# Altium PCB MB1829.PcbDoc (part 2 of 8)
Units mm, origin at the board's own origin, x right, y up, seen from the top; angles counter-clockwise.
Board outline 90 x 110 mm, 6 copper layers (Top Layer, Signal Layer 1, Signal Layer 2, Signal Layer 3, Signal Layer 4, Bottom Layer), stack 1.578 mm thick; 466 components, 354 nets, 2058 pads, 1522 vias.
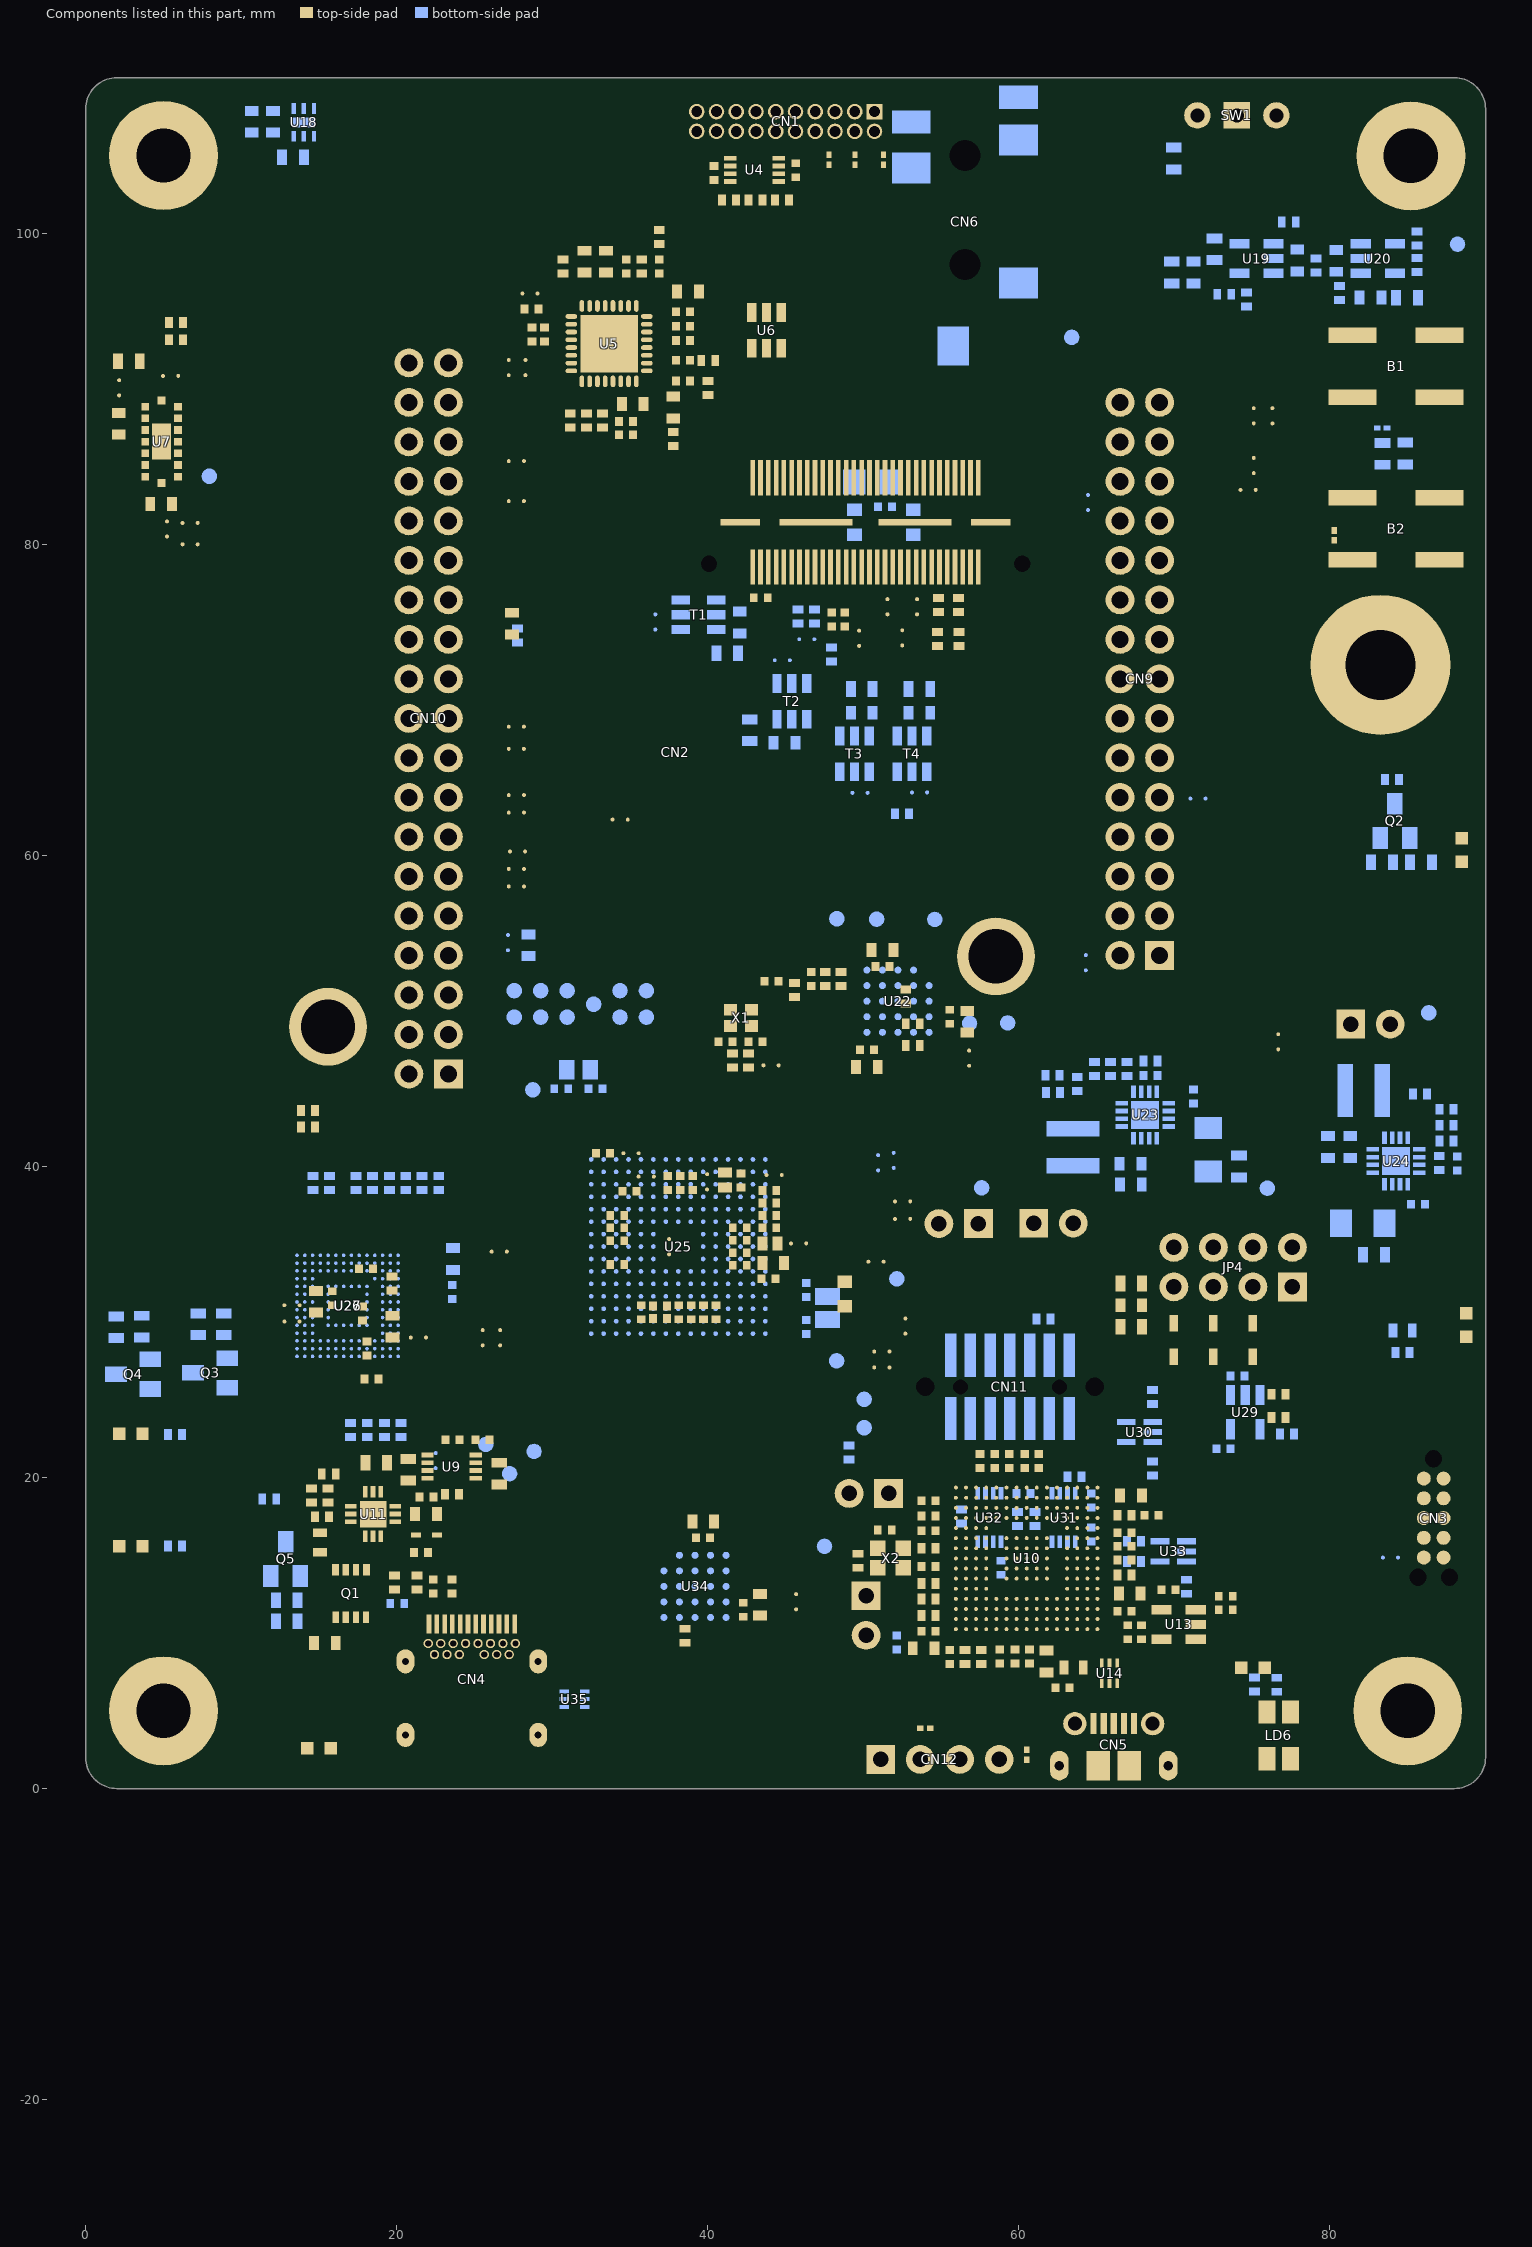
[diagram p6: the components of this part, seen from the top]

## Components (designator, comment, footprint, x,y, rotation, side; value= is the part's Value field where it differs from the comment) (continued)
LD3 "LED_green" LED_0603_OSRAM_LG-Q396-PS-35_GREEN_1A2K_H0P4 2.9,22.8 r180 top locked value=GREEN
LD4 "LED_red" LED_0603_OSRAM_LS-Q976-NR-1_RED_1A2K_H0P8 2.9,15.575 r180 top locked value=RED
LD5 "LED_red" LED_0603_OSRAM_LS-Q976-NR-1_RED_1A2K_H0P8 75.05,7.775 r0 top locked value=RED
LD6 "LED_BICOLOR" LED_BI-GR_WE-150141SV73110 76.7,3.425 r0 top locked value="Green / Red"
LD7 "LED_green" LED_0603_OSRAM_LG-Q396-PS-35_GREEN_1A2K_H0P4 15,2.6 r0 top locked value=GREEN
Q1 "STL11N3LLH6" MOS_POWERFLAT_3P3X3P3_P065 17.05,12.55 r0 top
Q2 "9013-SOT23" NPN_SOT23 84.175,62.225 r180 bottom value="NPN SOT23"
Q3 "9013-SOT23" NPN_SOT23 8,26.725 r270 bottom value="NPN SOT23"
Q4 "9013-SOT23" NPN_SOT23 3.047,26.641 r270 bottom value="NPN SOT23"
Q5 "9013-SOT23" NPN_SOT23 12.85,14.775 r180 bottom value="NPN SOT23"
R1 "Resistor" R0402 41.35,102.125 r0 top value=10K
R2 "Resistor" R0402 43.05,102.125 r0 top value=0R
R3 "Resistor" R0402 44.775,102.125 r180 top value=10K
R4 "Resistor" R0402 36.875,99.75 r270 top value=10K
R5 "Resistor" R0402 30.675,97.85 r270 top value=10K
R6 "Resistor" R0402 35.75,97.85 r270 top value=2K2
R7 "Resistor" R0402 5.8,94.25 r180 top value=1K8
R8 "Resistor" R0402 5.8,93.15 r180 top value=1K8
R9 "Resistor" R0603 2.775,91.775 r0 top value=10K
R10 "Resistor" R0402 40.025,91.825 r180 top value=51R
R11 "Resistor" R0402 40,90.05 r90 top value=51R
R12 "Resistor" R0402 33.225,87.95 r270 top value=10K
R13 "Resistor" R0402 31.15,87.95 r270 top value=1K8
R14 "Resistor" R0402 32.207,87.95 r270 top value=1K8
R15 "Resistor" R0402 37.775,86.775 r270 top value=0R
R16 "Resistor" R0402 54.825,76.1 r270 top value=0R
R17 "Resistor" R0402 56.125,76.1 r270 top value=0R
R18 "Resistor" R0402 56.15,73.925 r270 top value=0R
R19 "Resistor" R0402 54.775,73.9 r270 top value=0R
R20 "Resistor" R0402 47.55,52.05 r270 top value=10K
R21 "Resistor" R0402 48.55,52.05 r270 top value=10K
R22 "Resistor" R0402 45.567,51.355 r90 top value=0R
R23 "Resistor" R0402 52.725,50.925 r270 top value=0R
R24 "Resistor" R0402 53.175,49.175 r0 top value=0R
R25 "Resistor" R0402 53.175,47.775 r0 top value=10K
R26 "Resistor" R0402 42.625,46.8 r90 top value=0R
R27 "Resistor" R0402 41.575,46.8 r90 top value=0R
R28 "Resistor" R0402 14.3,43.6 r0 top value=1K8
R29 "Resistor" R0402 14.3,42.525 r0 top value=1K8
R30 "Resistor" R0402 19.7,32.475 r270 top value=47K
R31 "Resistor" R0603 67.225,32.475 r0 top value=330K
R32 "Resistor" R0603 67.225,29.7 r180 top value=27K
R33 "Resistor" R0402 76.7,25.35 r180 top value=100K
R34 "Resistor" R0402 76.7,23.85 r180 top value=1K
R35 "Resistor" R0603 20.725,20.5 r90 top value=47K
R36 "Resistor" R0603 18.675,20.95 r0 top value=10K
R37 "Resistor" R0603 26.6,20.25 r270 top value=47K
R38 "Resistor" R0402 15.625,20.225 r0 top value=3K9
R39 "Resistor" R0402 14.525,18.85 r270 top value=3K9
R40 "Resistor" R0402 15.575,18.85 r270 top value=1K2
R41 "Resistor" R0402 23.55,18.925 r180 top value=0R
R42 "Resistor" R0402 66.8,17.575 r0 top value=100R
R43 "Resistor" R0402 15.2,17.475 r0 top value=1K2
R44 "Resistor" R0402 54.2,15.45 r0 top value=100R
R45 "Resistor" R0402 49.65,14.65 r270 top value=10K
R46 "Resistor" R0402 66.8,13.725 r180 top value=3K
R47 "Resistor" R0402 19.85,13.25 r270 top value=2K4
R48 "Resistor" R0402 21.3,13.25 r270 top value=10K
R49 "Resistor" R0402 54.2,13.175 r0 top value=10K
R50 "Resistor" R0402 54.2,12.2 r180 top value=4K7
R51 "Resistor" R0402 54.2,11.125 r180 top value=4K7
R52 "Resistor" R0402 38.525,9.825 r270 top value=10K
R53 "Resistor" R0402 56.525,8.45 r90 top value=4K7
R54 "Resistor" R0402 57.575,8.45 r90 top value=2K7
R55 "Resistor" R0603 69.95,104.8 r90 bottom value=10K
R56 "Resistor" R0603 13.326,104.875 r180 bottom value=10K
R57 "Resistor" R0402 77.35,100.725 r180 bottom value=0R
R58 "Resistor" R0402 85.6,99.675 r270 bottom value=160K
R59 "Resistor" R0603 72.575,98.975 r270 bottom value=0R
R60 "Resistor" R0402 85.591,97.95 r270 bottom value=220K
R61 "Resistor" R0402 79.1,97.923 r90 bottom value=0R
R62 "Resistor" R0603 69.825,97.475 r90 bottom value=0R
R63 "Resistor" R0402 80.6,96.15 r90 bottom value=0R
R64 "Resistor" R0402 74.625,95.75 r90 bottom value=160K
R65 "Resistor" R0402 73.2,96.075 r180 bottom value=82K
R66 "Resistor" R0603 84.95,95.85 r180 bottom value=0R
R67 "Resistor" R0603 84.85,85.84 r90 bottom value=20K
R68 "Resistor" R0603 83.375,85.815 r90 bottom value=200R
R69 "Resistor" R0402 46.85,75.346 r90 bottom value=3K3
R70 "Resistor" R0402 45.8,75.346 r90 bottom value=3K3
R71 "Resistor" R0402 27.75,74.15 r270 bottom value=10K
R72 "Resistor" R0402 47.95,72.921 r90 bottom value=10K
R73 "Resistor" R0603 41.25,72.996 r180 bottom value=0R
R74 "Resistor" R0603 53.6,70.696 r0 bottom value=0R
R75 "Resistor" R0603 49.9,70.696 r0 bottom value=0R
R76 "Resistor" R0603 42.7,68.046 r90 bottom value=0R
R77 "Resistor" R0402 83.996,64.879 r180 bottom value=270R
R78 "Resistor" R0402 52.475,62.675 r0 bottom value=100K
R79 "Resistor" R0603 85.85,59.55 r180 bottom value=47K
R80 "Resistor" R0603 83.35,59.55 r0 bottom value=100K
R81 "Resistor" R0402 68.472,46.791 r0 bottom value=0R
R82 "Resistor" R0402 66.947,46.266 r270 bottom value=15K
R83 "Resistor" R0402 65.897,46.266 r90 bottom value=6K8
R84 "Resistor" R0402 64.847,46.266 r90 bottom value=12K
R85 "Resistor" R0402 62.172,45.866 r0 bottom value=0R
R86 "Resistor" R0402 63.747,45.291 r90 bottom value=100K
R87 "Resistor" R0402 62.197,44.766 r0 bottom value=1K
R88 "Resistor" R0402 85.8,44.65 r0 bottom value=100K
R89 "Resistor" R0402 87.5,43.675 r180 bottom value=0R
R90 "Resistor" R0402 87.5,42.65 r0 bottom value=47K
R91 "Resistor" R0402 87.5,41.625 r180 bottom value=15K
R92 "Resistor" R0603 74.15,40 r90 bottom value=0R
R93 "Resistor" R0402 87.025,40.225 r270 bottom value=0R
R95 "Resistor" R0402 22.7,38.925 r90 bottom value=47K
R96 "Resistor" R0402 21.625,38.925 r90 bottom value=47K
R97 "Resistor" R0402 20.575,38.925 r90 bottom value=47K
R98 "Resistor" R0402 19.525,38.925 r90 bottom value=47K
R99 "Resistor" R0402 18.45,38.925 r90 bottom value=47K
R100 "Resistor" R0402 17.375,38.925 r90 bottom value=47K
R101 "Resistor" R0402 15.675,38.925 r90 bottom value=47K
R102 "Resistor" R0402 14.625,38.925 r90 bottom value=47K
R103 "Resistor" R0603 82.825,34.325 r0 bottom value=0R
R104 "Resistor" R0603 8.875,29.85 r270 bottom value=100K
R105 "Resistor" R0603 7.225,29.85 r270 bottom value=47K
R106 "Resistor" R0603 3.6,29.7 r270 bottom value=100K
R107 "Resistor" R0603 1.972,29.666 r270 bottom value=47K
R108 "Resistor" R0402 61.575,30.2 r0 bottom value=100R
R109 "Resistor" R0402 84.65,28.05 r180 bottom value=620R
R110 "Resistor" R0402 68.6,25.175 r270 bottom value=47R
R111 "Resistor" R0402 20.275,23.05 r90 bottom value=0R
R112 "Resistor" R0402 19.2,23.05 r270 bottom value=10K
R113 "Resistor" R0402 18.1,23.05 r270 bottom value=10K
R114 "Resistor" R0402 17.025,23.05 r270 bottom value=10K
R115 "Resistor" R0402 77.25,22.8 r180 bottom value=10K
R116 "Resistor" R0402 5.75,22.775 r0 bottom value=270R
R117 "Resistor" R0402 49.075,21.6 r270 bottom value=47R
R118 "Resistor" R0402 68.6,20.575 r270 bottom value=47R
R119 "Resistor" R0402 63.575,20.05 r180 bottom value=100K
R120 "Resistor" R0402 11.8,18.625 r0 bottom value=270R
R121 "Resistor" R0402 56.3,17.5 r270 bottom value=0R
R122 "Resistor" R0402 61.025,17.325 r270 bottom value=0R
R123 "Resistor" R0402 59.9,17.325 r270 bottom value=100R
R124 "Resistor" R0402 67.4,15.9 r180 bottom value=47R
R125 "Resistor" R0402 5.75,15.6 r0 bottom value=270R
R126 "Resistor" R0402 67.4,14.6 r180 bottom value=47R
R127 "Resistor" R0402 70.775,12.975 r270 bottom value=47R
R128 "Resistor" R0603 12.925,12.1 r0 bottom value=22K
R129 "Resistor" R0603 12.925,10.75 r0 bottom value=47K
R130 "Resistor" R0402 75.15,6.7 r90 bottom value=1K
R131 "Resistor" R0402 76.575,6.675 r90 bottom value=330R
SB1 "SB_OFF" SOLDER-BRIDGE_R0402-0R 28.525,96.125 r0 top
SB2 "SB_OFF" SOLDER-BRIDGE_R0402-0R 28.275,91.325 r90 top
SB3 "SB_OFF" SOLDER-BRIDGE_R0402-0R 27.2,91.325 r90 top
SB4 "SB_ON" SOLDER-BRIDGE_R0402-0R 5.5,90.825 r180 top
SB5 "SB_ON" SOLDER-BRIDGE_R0402-0R 2.15,90.1 r270 top
SB6 "SB_ON" SOLDER-BRIDGE_R0402-0R 76.3,88.3 r270 top
SB7 "SB_OFF" SOLDER-BRIDGE_R0402-0R 75.1,88.3 r270 top
SB8 "SB_OFF" SOLDER-BRIDGE_R0402-0R 75.1,85.1 r270 top
SB9 "SB_ON" SOLDER-BRIDGE_R0402-0R 74.7,83.5 r0 top
SB10 "SB_OFF" SOLDER-BRIDGE_R0402-0R 27.725,85.35 r180 top
SB11 "SB_OFF" SOLDER-BRIDGE_R0402-0R 27.725,82.775 r180 top
SB12 "SB_OFF" SOLDER-BRIDGE_R0402-0R 5.225,80.95 r90 top
SB13 "SB_OFF" SOLDER-BRIDGE_R0402-0R 6.75,81.375 r180 top
SB14 "SB_OFF" SOLDER-BRIDGE_R0402-0R 51.55,76.021 r270 top
SB15 "SB_OFF" SOLDER-BRIDGE_R0402-0R 53.45,76.021 r270 top
SB16 "SB_OFF" SOLDER-BRIDGE_R0402-0R 52.5,74.021 r270 top
SB17 "SB_OFF" SOLDER-BRIDGE_R0402-0R 34.4,62.3 r180 top
SB18 "SB_OFF" SOLDER-BRIDGE_R0402-0R 49.725,73.996 r270 top
SB19 "SB_OFF" SOLDER-BRIDGE_R0402-0R 27.725,60.25 r0 top
SB20 "SB_ON" SOLDER-BRIDGE_R0402-0R 27.725,68.275 r180 top
SB21 "SB_ON" SOLDER-BRIDGE_R0402-0R 27.725,66.85 r180 top
SB22 "SB_OFF" SOLDER-BRIDGE_R0402-0R 27.725,63.875 r180 top
SB23 "SB_ON" SOLDER-BRIDGE_R0402-0R 27.725,62.75 r180 top
SB24 "SB_ON" SOLDER-BRIDGE_R0402-0R 27.725,59.125 r180 top
SB25 "SB_OFF" SOLDER-BRIDGE_R0402-0R 27.725,58 r180 top
SB26 "SB_ON" SOLDER-BRIDGE_R0402-0R 76.675,47.975 r90 top
SB27 "SB_ON" SOLDER-BRIDGE_R0402-0R 56.8,46.925 r90 top
SB28 "SB_OFF" SOLDER-BRIDGE_R0402-0R 44.1,46.5 r180 top
SB29 "SB_ON" SOLDER-BRIDGE_R0402-0R 35.1,40.85 r180 top
SB30 "SB_ON" SOLDER-BRIDGE_R0402-0R 39.95,39.05 r270 top
SB31 "SB_ON" SOLDER-BRIDGE_R0402-0R 44.225,39.45 r0 top
SB32 "SB_ON" SOLDER-BRIDGE_R0402-0R 36,39.35 r0 top
SB33 "SB_ON" SOLDER-BRIDGE_R0402-0R 52.563,37.75 r180 top
SB34 "SB_OFF" SOLDER-BRIDGE_R0402-0R 52.563,36.625 r180 top
SB35 "SB_OFF" SOLDER-BRIDGE_R0402-0R 37.506,34.875 r270 top
SB36 "SB_ON" SOLDER-BRIDGE_R0402-0R 45.875,35.05 r180 top
SB37 "SB_ON" SOLDER-BRIDGE_R0402-0R 26.55,34.525 r0 top
SB38 "SB_OFF" SOLDER-BRIDGE_R0402-0R 50.772,33.875 r0 top
SB39 "SB_OFF" SOLDER-BRIDGE_R0402-0R 13.225,31.075 r0 top
SB40 "SB_OFF" SOLDER-BRIDGE_R0402-0R 52.7,29.775 r270 top
SB41 "SB_ON" SOLDER-BRIDGE_R0402-0R 13.225,30.025 r0 top
SB42 "SB_ON" SOLDER-BRIDGE_R0402-0R 25.525,28.95 r90 top
SB43 "SB_OFF" SOLDER-BRIDGE_R0402-0R 26.65,28.95 r90 top
SB44 "SB_ON" SOLDER-BRIDGE_R0402-0R 21.425,29 r180 top
SB45 "SB_ON" SOLDER-BRIDGE_R0402-0R 51.225,28.1 r180 top
SB46 "SB_OFF" SOLDER-BRIDGE_R0402-0R 51.225,27.075 r180 top
SB47 "SB_ON" SOLDER-BRIDGE_R0402-0R 45.675,11.975 r90 top
SB48 "SB_ON" SOLDER-BRIDGE_R0402-0R 64.45,82.725 r270 bottom
SB49 "SB_ON" SOLDER-BRIDGE_R0402-0R 36.625,74.971 r90 bottom
SB50 "SB_ON" SOLDER-BRIDGE_R0402-0R 46.325,73.896 r0 bottom
SB51 "SB_ON" SOLDER-BRIDGE_R0402-0R 44.75,72.546 r0 bottom
SB52 "SB_ON" SOLDER-BRIDGE_R0402-0R 53.65,64.046 r180 bottom
SB53 "SB_ON" SOLDER-BRIDGE_R0402-0R 49.825,64.021 r180 bottom
SB54 "SB_ON" SOLDER-BRIDGE_R0402-0R 71.55,63.65 r180 bottom
SB55 "SB_ON" SOLDER-BRIDGE_R0402-0R 27.15,54.35 r90 bottom
SB56 "SB_ON" SOLDER-BRIDGE_R0402-0R 64.3,53.063 r90 bottom
SB57 "SB_ON" SOLDER-BRIDGE_R0402-0R 51.95,40.427 r270 bottom
SB58 "SB_ON" SOLDER-BRIDGE_R0402-0R 50.95,40.2 r90 bottom
SB59 "SB_ON" SOLDER-BRIDGE_R0402-0R 22.5,21.05 r90 bottom
SB60 "SB_ON" SOLDER-BRIDGE_R0402-0R 6.75,80 r180 top
SB61 "SB_ON" SOLDER-BRIDGE_R0402-0R 83.85,14.85 r0 bottom
SW1 "SW_MECA_1K2" SWI_EAO_09-03290-01_EXTENDED_STRAIGHT_BLACK 74.015,107.575 r270 bottom value="Mechanical Slide Switch 1K2"
T1 "PMN30XP" MOS_SOT23-6L 39.4,75.471 r270 bottom
T2 "PMN30XP" MOS_SOT23-6L 45.4,69.896 r180 bottom
T3 "PMN30XP" MOS_SOT23-6L 49.425,66.521 r0 bottom
T4 "PMN30XP" MOS_SOT23-6L 53.125,66.521 r0 bottom
TP1 "Test Point" TP_SMD_1MM 88.2,99.3 r180 bottom
TP2 "Test Point" TP_SMD_1MM 63.394,93.3 r270 bottom
TP3 "Test Point" TP_SMD_1MM 7.95,84.375 r270 bottom
TP4 "Test Point" TP_SMD_1MM 48.3,55.925 r0 bottom
TP5 "Test Point" TP_SMD_1MM 50.85,55.9 r0 bottom
TP6 "Test Point" TP_SMD_1MM 54.592,55.879 r0 bottom
TP7 "Test Point" TP_SMD_1MM 36.053,51.304 r270 bottom
TP8 "Test Point" TP_SMD_1MM 34.353,51.304 r270 bottom
TP9 "Test Point" TP_SMD_1MM 30.953,51.304 r270 bottom
TP10 "Test Point" TP_SMD_1MM 29.253,51.304 r270 bottom
TP11 "Test Point" TP_SMD_1MM 27.553,51.304 r270 bottom
TP12 "Test Point" TP_SMD_1MM 32.653,50.429 r270 bottom
TP13 "Test Point" TP_SMD_1MM 86.35,49.875 r180 bottom
TP14 "Test Point" TP_SMD_1MM 36.053,49.604 r270 bottom
TP15 "Test Point" TP_SMD_1MM 34.353,49.604 r270 bottom
TP16 "Test Point" TP_SMD_1MM 30.953,49.604 r270 bottom
TP17 "Test Point" TP_SMD_1MM 29.253,49.604 r270 bottom
TP18 "Test Point" TP_SMD_1MM 27.553,49.604 r270 bottom
TP19 "Test Point" TP_SMD_1MM 59.275,49.225 r180 bottom
TP20 "Test Point" TP_SMD_1MM 56.825,49.2 r270 bottom
TP21 "Test Point" TP_SMD_1MM 28.75,44.925 r0 bottom
TP22 "Test Point" TP_SMD_1MM 57.6,38.625 r0 bottom
TP23 "Test Point" TP_SMD_1MM 75.975,38.6 r270 bottom
TP24 "Test Point" TP_SMD_1MM 52.152,32.774 r0 bottom
TP25 "Test Point" TP_SMD_1MM 48.275,27.5 r0 bottom
TP26 "Test Point" TP_SMD_1MM 50.05,25.025 r90 bottom
TP27 "Test Point" TP_SMD_1MM 50.05,23.2 r90 bottom
TP28 "Test Point" TP_SMD_1MM 25.728,22.125 r0 bottom
TP29 "Test Point" TP_SMD_1MM 28.825,21.675 r90 bottom
TP30 "Test Point" TP_SMD_1MM 27.25,20.25 r90 bottom
TP31 "Test Point" TP_SMD_1MM 47.5,15.575 r0 bottom
U1 "ESD-TRANSIL" ESD_ST0201 47.8,104.725 r270 top value=ESDALC6V1-1U2
U2 "ESD-TRANSIL" ESD_ST0201 49.45,104.725 r270 top value=ESDALC6V1-1U2
U3 "ESD-TRANSIL" ESD_ST0201 51.3,104.725 r270 top value=ESDALC6V1-1U2
U4 "SN74LVC2T45DCUT" ICC_VSSOP8_DCU_R-PDSO-G8_2X2P30_P050 43,104.075 r90 top
U5 "CS42L51-CNZ" ICC_QFN32-EPAD_5X5_P050 33.65,92.9 r0 top
U6 "ESDA6V1BC6" ESD_SOT23-6L 43.775,93.75 r180 top
U7 "VL53L5CXV0GC/1" ICC_LGA16_6P4X3_P075_H1P5 4.875,86.6 r270 top
U8 "ESD-TRANSIL" ESD_ST0201 80.275,80.575 r270 top value=ESDALC6V1-1U2
U9 "SN74LVC2T45DCUT" ICC_VSSOP8_DCU_R-PDSO-G8_2X2P30_P050 23.525,20.7 r270 top
U10 "ST-LINKV3E_SWD" ICC_UFBGA201_176+25_10X10_P065 60.5,14.8 r0 top
U11 "TCPP01-M12" ICC_QFN12L-EPAD_3X3_P050 18.475,17.65 r270 top
U12 "ESD-TRANSIL" ESD_QFN1610_2N_1K_2A 15.05,15.825 r90 top value=ESDA25P35-1U1M
U13 "LD3985M33R" REG_SOT23-5L 70.275,10.55 r90 top
U14 "ECMF02-2AMX6" ESD_QFN-6L_1P7X1P5_P050 65.825,7.425 r180 top
U15 "ESD-TRANSIL" ESD_QFN1610_2N_1K_2A 63.525,7.775 r180 top value=ESDA7P120-1U1M
U16 "ESD-TRANSIL" ESD_ST0201 53.975,3.875 r0 top value=ESDALC6V1-1U2
U17 "ESD-TRANSIL" ESD_ST0201 60.5,2.175 r90 top value=ESDALC6V1-1U2
U18 "STTS22H" ICC_UDFN6-EPAD_2X2_P065 14.025,107.125 r180 bottom
U19 "TPS76301" ICC_SOT23-5L_H1P45 75.275,98.375 r270 bottom
U20 "TPS76301" ICC_SOT23-5L_H1P45 83.075,98.375 r90 bottom
U21 "ESD-TRANSIL" ESD_ST0201 83.35,87.475 r180 bottom value=ESDALC6V1-1U2
U22 "MX25xx51245GXDx00" ICC_BGA24_5X5-BALL-ARRAY_6X8_P1 52.225,50.625 r180 bottom value=MX25UM51245GXDI00
U23 "TPS62140RGTR" ICC_VQFN16-EPAD_3X3_P050 68.122,43.314 r90 bottom value=TPS62140
U24 "TPS62140RGTR" ICC_VQFN16-EPAD_3X3_P050 84.25,40.35 r0 bottom value=TPS62140
U25 "STM32U599NJH6Q_BGA216_SMPS" ICC_TFBGA216_13X13_P080_H1P10_CODE-A0L2 38.1,34.85 r270 bottom locked value=STM32U599NJH6Q
U26 "MTFC4GACAJCN-1M WT" ICC_P-WFBGA153_13X11P5_P050 16.835,31.036 r270 bottom
U27 "eMMC_THGBMTG5D1LBAIL" ICC_P-WFBGA153_13X11P5_P050 16.835,31.036 r270 bottom value=THGBMTG5D1LBAIL
U28 "ESD-TRANSIL" ESD_QFN1610_2N_1K_2A 84.675,29.45 r0 bottom value=ESDA7P120-1U1M
U29 "STMPS2151STR" MOS_SOT23-5L 74.55,24.2 r0 bottom
U30 "ESDALC6V1W5" ESD_SOT323-5L 67.75,22.925 r270 bottom
U31 "SN74LVC2T45DCUT" ICC_VSSOP8_DCU_R-PDSO-G8_2X2P30_P050 62.875,17.425 r180 bottom
U32 "SN74LVC2T45DCUT" ICC_VSSOP8_DCU_R-PDSO-G8_2X2P30_P050 58.1,17.425 r180 bottom
U33 "ESDALC6V1W5" ESD_SOT323-5L 69.925,15.25 r270 bottom
U34 "APS256XXN-OBR-BG" ICC_BGA24_5X5-BALL-ARRAY_6X8_P1 39.175,13 r270 bottom value=APS512XXN-OBR-BG
U35 "ECMF02-2AMX6" ESD_QFN-6L_1P7X1P5_P050 31.425,5.75 r270 bottom
X1 "XTAL_4_PINS" CRY_NX2016SA_4P 42.125,49.55 r180 top value=16MHz
X2 "OSCILLATOR_4_PINS" OSC_NDK_NZ2520SB_4P 51.75,14.825 r0 top value=25MHz
X3 "XTAL_2_PINS" CRY_NX2012SA_2P 31.675,46.225 r180 bottom value=32.768KHz

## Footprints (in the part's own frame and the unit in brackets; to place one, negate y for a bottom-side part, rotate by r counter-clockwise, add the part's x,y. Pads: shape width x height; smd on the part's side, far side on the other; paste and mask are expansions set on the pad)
C0402 [mm]
  rect 0.51x0.56 smd mask+0.05: 1(-0.45,0) 2(0.45,0)
  body extent -0.5,-0.3 0.5,0.3, height 0.4
C0603 [mm]
  rect 0.64x0.89 smd mask+0.05: 1(-0.7,0) 2(0.7,0)
  silkscreen extent -0.9,-0.55 1.05,0.55, body extent -0.9,-0.5 0.9,0.5, height 1.4
C0603_H0P8 [mm] "MCD-01540"
  rect 0.64x0.89 smd mask+0.05: 1(-0.7,0) 2(0.7,0)
  silkscreen extent -0.9,-0.55 0.9,0.55, body extent -0.9,-0.5 0.9,0.5, height 1
C1206_H1P6 [mm]
  rect 1.4x1.78 smd mask+0.05: 1(-1.4,0) 2(1.4,0)
  silkscreen extent -2.12,-0.97 2.15,0.97, body extent -1.7,-0.9 1.7,0.9, height 1.8
CON_FCI_20021311-XXX20XXLF [mm]
  rect 1x1 / inner round 1 / far side rect 1x1 hole 0.7 mask+0.05: 1(5.715,0.635)
  round 1 hole 0.7 mask+0.05: 2(5.715,-0.635) 3(4.445,0.635) 4(4.445,-0.635) 5(3.175,0.635) 6(3.175,-0.635) 7(1.905,0.635) 8(1.905,-0.635) 9(0.635,0.635) 10(0.635,-0.635) 11(-0.635,0.635) 12(-0.635,-0.635) 13(-1.905,0.635) 14(-1.905,-0.635) 15(-3.175,0.635) 16(-3.175,-0.635) 17(-4.445,0.635) 18(-4.445,-0.635) 19(-5.715,0.635) 20(-5.715,-0.635)
  silkscreen extent -6.58,-1.5 6.58,1.5, body extent -6.58,-1.5 6.58,1.5, height 4.4
CON_PHONE-JACK-3P5_HY_PJ3028B [mm]
  rect 1.5x2.5 smd mask+0.05: 2(1.25,-3.45) 7(2.85,3.45)
  rect 2x2.5 smd mask+0.05: 3(4,-3.45) 4(5.8,3.45) 6(13.2,-3.45)
  rect 2.5x2 smd mask+0.05: 5(17.25,0.75)
  round 0.5 hole 2 unplated mask+0.1: MT1(5,0) MT2(12,0)
  Multi-Layer keep-out circle w0.01: c12,0 r1.25
  Multi-Layer keep-out circle w0.01: c5,0 r1.25
  silkscreen extent -0.9,-3.7 16,3, body extent -0.9,-3 16,3, height 5
CON_SAMTEC_QSH-030-01-F-D-A_NO-LCD-MB1835 [mm] "MCD-02128"
  round 5 hole 3.2: 1(3.5,3.5) PTH2(46.44,8.031)
  rect 0.3x2.27 smd mask+0.05: 1(45.31,38.801) 2(45.31,33.061) 3(44.81,38.801) 4(44.81,33.061) 5(44.31,38.801) 6(44.31,33.061) 7(43.81,38.801) 8(43.81,33.061) 9(43.31,38.801) 10(43.31,33.061) 11(42.81,38.801) 12(42.81,33.061) 13(42.31,38.801) 14(42.31,33.061) 15(41.81,38.801) 16(41.81,33.061) 17(41.31,38.801) 18(41.31,33.061) 19(40.81,38.801) 20(40.81,33.061) 21(40.31,38.801) 22(40.31,33.061) 23(39.81,38.801) 24(39.81,33.061) 25(39.31,38.801) 26(39.31,33.061) 27(38.81,38.801) 28(38.81,33.061) 29(38.31,38.801) 30(38.31,33.061) 31(37.81,38.801) 32(37.81,33.061) 33(37.31,38.801) 34(37.31,33.061) 35(36.81,38.801) 36(36.81,33.061) 37(36.31,38.801) 38(36.31,33.061) 39(35.81,38.801) 40(35.81,33.061) 41(35.31,38.801) 42(35.31,33.061) 43(34.81,38.801) 44(34.81,33.061) 45(34.31,38.801) 46(34.31,33.061) 47(33.81,38.801) 48(33.81,33.061) 49(33.31,38.801) 50(33.31,33.061) 51(32.81,38.801) 52(32.81,33.061) 53(32.31,38.801) 54(32.31,33.061) 55(31.81,38.801) 56(31.81,33.061) 57(31.31,38.801) 58(31.31,33.061) 59(30.81,38.801) 60(30.81,33.061)
  rect 2.54x0.43 smd mask+0.05: 61(46.122,35.931) 64(29.997,35.931)
  rect 4.7x0.43 smd mask+0.05: 62(41.235,35.931) 63(34.885,35.931)
  round 0.5 hole 1.05 unplated mask+0.1: 65(27.995,33.261) 66(48.125,33.261)
  Multi-Layer keep-out circle w0.01: c48.125,33.261 r0.801
  Multi-Layer keep-out circle w0.01: c27.995,33.261 r0.801
  silkscreen extent 27.26,32.23 48.86,39.63, body extent 27.4,32.18 48.72,39.68, height 4.97
CON_SAMTEC_SSW-115-21-F-D [mm] "MCD-02943"
  rect 1.85x1.85 / inner round 1.85 / far side rect 1.85x1.85 hole 1.1 mask+0.05: 1(17.78,-1.27)
  round 1.85 hole 1.1 mask+0.05: 2(17.78,1.27) 3(15.24,-1.27) 4(15.24,1.27) 5(12.7,-1.27) 6(12.7,1.27) 7(10.16,-1.27) 8(10.16,1.27) 9(7.62,-1.27) 10(7.62,1.27) 11(5.08,-1.27) 12(5.08,1.27) 13(2.54,-1.27) 14(2.54,1.27) 15(0,-1.27) 16(0,1.27) 17(-2.54,-1.27) 18(-2.54,1.27) 19(-5.08,-1.27) 20(-5.08,1.27) 21(-7.62,-1.27) 22(-7.62,1.27) 23(-10.16,-1.27) 24(-10.16,1.27) 25(-12.7,-1.27) 26(-12.7,1.27) 27(-15.24,-1.27) 28(-15.24,1.27) 29(-17.78,-1.27) 30(-17.78,1.27)
  silkscreen extent -19.31,-2.47 19.31,2.47, body extent -19.3,-2.48 19.3,2.48, height 8.51
CON_SAMTEC_SSW-119-21-F-D [mm] "MCD-02944"
  rect 1.85x1.85 / inner round 1.85 / far side rect 1.85x1.85 hole 1.1 mask+0.05: 1(22.86,-1.27)
  round 1.85 hole 1.1 mask+0.05: 2(22.86,1.27) 3(20.32,-1.27) 4(20.32,1.27) 5(17.78,-1.27) 6(17.78,1.27) 7(15.24,-1.27) 8(15.24,1.27) 9(12.7,-1.27) 10(12.7,1.27) 11(10.16,-1.27) 12(10.16,1.27) 13(7.62,-1.27) 14(7.62,1.27) 15(5.08,-1.27) 16(5.08,1.27) 17(2.54,-1.27) 18(2.54,1.27) 19(0,-1.27) 20(0,1.27) 21(-2.54,-1.27) 22(-2.54,1.27) 23(-5.08,-1.27) 24(-5.08,1.27) 25(-7.62,-1.27) 26(-7.62,1.27) 27(-10.16,-1.27) 28(-10.16,1.27) 29(-12.7,-1.27) 30(-12.7,1.27) 31(-15.24,-1.27) 32(-15.24,1.27) 33(-17.78,-1.27) 34(-17.78,1.27) 35(-20.32,-1.27) 36(-20.32,1.27) 37(-22.86,-1.27) 38(-22.86,1.27)
  silkscreen extent -24.39,-2.47 24.39,2.47, body extent -24.38,-2.48 24.38,2.48, height 8.51
CON_SAMTEC_TSW-102-07-G-S [mm]
  rect 1.85x1.85 / inner round 1.85 / far side rect 1.85x1.85 hole 1 mask+0.05: 1(-1.27,0)
  round 1.85 hole 1 mask+0.05: 2(1.27,0)
  silkscreen extent -2.58,-1.3 2.58,1.3, body extent -2.67,-1.3 2.58,1.3, height 8.38
CON_SAMTEC_TSW-104-07-G-S [mm]
  rect 1.85x1.85 / inner round 1.85 / far side rect 1.85x1.85 hole 1 mask+0.05: 1(-3.81,0)
  round 1.85 hole 1 mask+0.05: 2(-1.27,0) 3(1.27,0) 4(3.81,0)
  silkscreen extent -5.12,-1.3 5.12,1.3, body extent -5.21,-1.37 5.18,1.37, height 8.38
CON_SAMTEC_TSW-104-07-X-D [mm]
  rect 1.85x1.85 / inner round 1.85 / far side rect 1.85x1.85 hole 1 mask+0.05: 1(-3.81,-1.27)
  round 1.85 hole 1 mask+0.05: 2(-3.81,1.27) 3(-1.27,-1.27) 4(-1.27,1.27) 5(1.27,-1.27) 6(1.27,1.27) 7(3.81,-1.27) 8(3.81,1.27)
  silkscreen extent -5.08,-2.54 5.08,2.54, body extent -5.08,-2.54 5.08,2.54, height 8.38
CON_STDC14_Receiver_MEDIUM__3D_FTSH-105-01-L-DV-K [mm] "MCD-02021 compatible with FTSH-105-01-L-DV-K"
  round 0 hole 1.19 unplated mask+0.05: 0(-5.445,0) 0(5.445,0)
  round 0 hole 0.97 unplated mask+0.05: 0(-3.175,0) 0(3.175,0)
  rect 0.74x2.79 smd mask+0.05: 1(-3.81,-2.032) 2(-3.81,2.032) 3(-2.54,-2.032) 4(-2.54,2.032) 5(-1.27,-2.032) 6(-1.27,2.032) 7(0,-2.032) 8(0,2.032) 9(1.27,-2.032) 10(1.27,2.032) 11(2.54,-2.032) 12(2.54,2.032) 13(3.81,-2.032) 14(3.81,2.032)
  silkscreen extent -6.3,-2.39 6.3,2.39, body extent -6.3,-2.92 6.3,2.92, height 6.6
CON_TAG-C_TC2050-IDC-NL [mm]
  round 0.9 smd paste+0 mask+0.05: 1(-2.54,-0.635) 2(-1.27,-0.635) 3(0,-0.635) 4(1.27,-0.635) 5(2.54,-0.635) 6(2.54,0.635) 7(1.27,0.635) 8(0,0.635) 9(-1.27,0.635) 10(-2.54,0.635)
  round 0 hole 1.1 unplated mask+0.05: 11(-3.81,0) 12(3.81,-1.015) 13(3.81,1.015)
  silkscreen extent -6.22,-3.4 6.22,3.33, body extent -6.28,-3.46 6.28,3.39, height 13
CON_USB-TYPEC_COXOC_317JD24BZTF3K3C3 [mm]
  rect 0.3x1.2 smd mask+0.05: A1(-2.75,10.58) A2(-2.25,10.58) A3(-1.75,10.58) A4(-1.25,10.58) A5(-0.75,10.58) A6(-0.25,10.58) A7(0.25,10.58) A8(0.75,10.58) A9(1.25,10.58) A10(1.75,10.58) A11(2.25,10.58) A12(2.75,10.58)
  round 0.6 hole 0.4 mask+0.05: B1(2,9.33) B1(2.8,9.33) B2(2.4,8.62) B3(1.6,8.62) B4(1.2,9.33) B5(0.8,8.62) B6(0.4,9.33) B7(-0.4,9.33) B8(-0.8,8.62) B9(-1.2,9.33) B10(-1.6,8.62) B11(-2.4,8.62) B12(-2.8,9.33) B12(-2,9.33)
  oval 1.15x1.55 hole 0.45 slot 0.85 at 90 deg mask+0.05: SH1(-4.27,8.18) SH2(-4.27,3.45) SH3(4.27,8.18) SH4(4.27,3.45)
  silkscreen extent -4.38,-0.95 4.38,10.38, body extent -4.38,-0.95 4.38,10.84, height 3.03
CON_USBMICROB_MOLEX_105017-0001_H2P90 [mm]
  rect 0.4x1.35 smd mask+0.05: 1(-1.3,4.15) 2(-0.65,4.15) 3(0,4.15) 4(0.65,4.15) 5(1.3,4.15)
  round 1.5 hole 0.9 mask+0.05: 6(-2.5,4.15) 7(2.5,4.15)
  oval 1.2x1.9 hole 0.6 slot 1.3 at 90 deg mask+0.05: 8(3.5,1.45) 9(-3.5,1.45)
  rect 1.5x1.9 smd mask+0.05: 10(-1,1.45) 11(1,1.45)
  Top Layer region: 2.3,2.4 3.5,2.4 3.5,0.5 2.3,0.5 2.3,2.4
  Top Layer region: -3.5,2.4 -2.3,2.4 -2.3,0.5 -3.5,0.5 -3.5,2.4
  silkscreen extent -4,-0.7 4,4.6, body extent -4.1,-1.15 4.1,4.66, height 2.9
CPOL_TAJ-A_1206_H180 [mm]
  rect 1.45x1.6 smd mask+0.05: 1(-1.175,0) 2(1.175,0)
  silkscreen extent -2.15,-1.05 1.7,1.05, body extent -1.7,-0.9 1.7,0.9, height 1.8
CRY_NX2012SA_2P [mm]
  rect 1x1.25 smd mask+0.05: 1(-0.75,0) 2(0.75,0)
  silkscreen extent -1.05,-0.75 1.05,0.75, body extent -1.05,-0.63 1.05,0.63, height 0.6
CRY_NX2016SA_4P [mm]
  rect 0.85x0.75 smd mask+0.05: 1(-0.675,-0.525) 2(0.675,-0.525) 3(0.675,0.525) 4(-0.675,0.525)
  silkscreen extent -1.22,-1.02 1.05,0.85, body extent -1.05,-0.85 1.05,0.85, height 0.7
DIO_SOD323 [mm]
  rect 1.06x0.54 smd mask+0.05: 1(-1.07,0) 2(1.07,0)
  silkscreen extent -0.9,-0.72 0.9,0.72, body extent -1.3,-0.78 1.3,0.78, height 1.17
DIO_SOD523_1A_2K [mm] "MCD-01677"
  rect 0.65x0.3 smd mask+0.05: 1(-0.675,0) 2(0.675,0)
  silkscreen extent -0.65,-0.45 1.05,0.55, body extent -0.85,-0.45 0.85,0.45, height 0.71
ESD_QFN1610_2N_1K_2A [mm] "DFN, 2-Leads, Body 1.60x1.00mm"
  rect 0.55x0.9 smd mask+0.05: 1(-0.625,0) 2(0.625,0)
  silkscreen extent -1.02,-0.58 0.85,0.58, body extent -0.85,-0.55 0.85,0.55, height 0.6
ESD_QFN-6L_1P7X1P5_P050 [mm]
  rect 0.25x0.6 smd mask+0.05: 1(-0.5,-0.65) 2(0,-0.65) 3(0.5,-0.65) 4(0.5,0.65) 5(0,0.65) 6(-0.5,0.65)
  silkscreen extent -0.9,-0.8 0.9,0.8, body extent -0.9,-0.8 0.9,0.8, height 0.56
ESD_SOT23-6L [mm]
  rect 0.6x1.2 smd mask+0.05: 1(-0.95,-1.15) 2(0,-1.15) 3(0.95,-1.15) 4(0.95,1.15) 5(0,1.15) 6(-0.95,1.15)
  silkscreen extent -1.53,-0.87 1.53,0.87, body extent -1.52,-1.5 1.52,1.5, height 1.45
ESD_SOT323-5L [mm]
  rect 0.4x1.2 smd mask+0.05: 1(-0.65,-0.85) 2(0,-0.85) 3(0.65,-0.85) 4(0.65,0.85) 5(-0.65,0.85)
  silkscreen extent -1.22,-1.21 1.22,0.77, body extent -1.15,-1.05 1.15,1.05, height 1.1
ESD_ST0201 [mm]
  rect 0.425x0.33 smd mask+0.05: 1(-0.312,0) 2(0.312,0)
  silkscreen extent -0.55,-0.3 -0.5,0.3, body extent -0.34,-0.18 0.34,0.18, height 0.34
FIL_0603_H0P65 [mm]
  rect 0.8x0.95 smd mask+0.05: 1(-0.8,0) 2(0.8,0)
  silkscreen extent -1.33,-0.6 1.33,0.6, body extent -0.87,-0.47 0.87,0.47, height 0.65
ICC_BGA24_5X5-BALL-ARRAY_6X8_P1 [mm]
  round 0.45 smd mask+0.05: A2(-1,2) A3(0,2) A4(1,2) A5(2,2) B1(-2,1) B2(-1,1) B3(0,1) B4(1,1) B5(2,1) C1(-2,0) C2(-1,0) C3(0,0) C4(1,0) C5(2,0) D1(-2,-1) D2(-1,-1) D3(0,-1) D4(1,-1) D5(2,-1) E1(-2,-2) E2(-1,-2) E3(0,-2) E4(1,-2) E5(2,-2)
  silkscreen extent -3.05,-4.05 3.05,4.05, body extent -3.05,-4.05 3.05,4.05, height 1.2
ICC_LGA16_6P4X3_P075_H1P5 [mm] "MCD-02257"
  rect 0.5x0.5 smd mask+0.05: A1(2.25,-1.05) A2(1.5,-1.05) A3(0.75,-1.05) A4(0,-1.05) A5(-0.75,-1.05) A6(-1.5,-1.05) A7(-2.25,-1.05) B1(2.65,0) B7(-2.65,0) C1(2.25,1.05) C2(1.5,1.05) C3(0.75,1.05) C4(0,1.05) C5(-0.75,1.05) C6(-1.5,1.05) C7(-2.25,1.05)
  rect 2.316x1.2 smd mask+0.05: B4(0,0)
  silkscreen extent -3.1,-1.5 3.1,1.5, body extent -3.1,-1.5 3.1,1.5, height 1.51
ICC_P-WFBGA153_13X11P5_P050 [mm]
  round 0.23 smd mask+0.05: A1(-3.25,-3.25) A2(-3.25,-2.75) A3(-3.25,-2.25) A4(-3.25,-1.75) A5(-3.25,-1.25) A6(-3.25,-0.75) A7(-3.25,-0.25) A8(-3.25,0.25) A9(-3.25,0.75) A10(-3.25,1.25) A11(-3.25,1.75) A12(-3.25,2.25) A13(-3.25,2.75) A14(-3.25,3.25) B1(-2.75,-3.25) B2(-2.75,-2.75) B3(-2.75,-2.25) B4(-2.75,-1.75) B5(-2.75,-1.25) B6(-2.75,-0.75) B7(-2.75,-0.25) B8(-2.75,0.25) B9(-2.75,0.75) B10(-2.75,1.25) B11(-2.75,1.75) B12(-2.75,2.25) B13(-2.75,2.75) B14(-2.75,3.25) C1(-2.25,-3.25) C2(-2.25,-2.75) C3(-2.25,-2.25) C4(-2.25,-1.75) C5(-2.25,-1.25) C6(-2.25,-0.75) C7(-2.25,-0.25) C8(-2.25,0.25) C9(-2.25,0.75) C10(-2.25,1.25) C11(-2.25,1.75) C12(-2.25,2.25) C13(-2.25,2.75) C14(-2.25,3.25) D1(-1.75,-3.25) D2(-1.75,-2.75) D3(-1.75,-2.25) D4(-1.75,-1.75) D12(-1.75,2.25) D13(-1.75,2.75) D14(-1.75,3.25) E1(-1.25,-3.25) E2(-1.25,-2.75) E3(-1.25,-2.25) E5(-1.25,-1.25) E6(-1.25,-0.75) E7(-1.25,-0.25) E8(-1.25,0.25) E9(-1.25,0.75) E10(-1.25,1.25) E12(-1.25,2.25) E13(-1.25,2.75) E14(-1.25,3.25) F1(-0.75,-3.25) F2(-0.75,-2.75) F3(-0.75,-2.25) F5(-0.75,-1.25) F10(-0.75,1.25) F12(-0.75,2.25) F13(-0.75,2.75) F14(-0.75,3.25) G1(-0.25,-3.25) G2(-0.25,-2.75) G3(-0.25,-2.25) G5(-0.25,-1.25) G10(-0.25,1.25) G12(-0.25,2.25) G13(-0.25,2.75) G14(-0.25,3.25) H1(0.25,-3.25) H2(0.25,-2.75) H3(0.25,-2.25) H5(0.25,-1.25) H10(0.25,1.25) H12(0.25,2.25) H13(0.25,2.75) H14(0.25,3.25) J1(0.75,-3.25) J2(0.75,-2.75) J3(0.75,-2.25) J5(0.75,-1.25) J10(0.75,1.25) J12(0.75,2.25) J13(0.75,2.75) J14(0.75,3.25) K1(1.25,-3.25) K2(1.25,-2.75) K3(1.25,-2.25) K5(1.25,-1.25) K6(1.25,-0.75) K7(1.25,-0.25) K8(1.25,0.25) K9(1.25,0.75) K10(1.25,1.25) K12(1.25,2.25) K13(1.25,2.75) K14(1.25,3.25) L1(1.75,-3.25) L2(1.75,-2.75) L3(1.75,-2.25) L12(1.75,2.25) L13(1.75,2.75) L14(1.75,3.25) M1(2.25,-3.25) M2(2.25,-2.75) M3(2.25,-2.25) M4(2.25,-1.75) M5(2.25,-1.25) M6(2.25,-0.75) M7(2.25,-0.25) M8(2.25,0.25) M9(2.25,0.75) M10(2.25,1.25) M11(2.25,1.75) M12(2.25,2.25) M13(2.25,2.75) M14(2.25,3.25) N1(2.75,-3.25) N2(2.75,-2.75) N3(2.75,-2.25) N4(2.75,-1.75) N5(2.75,-1.25) N6(2.75,-0.75) N7(2.75,-0.25) N8(2.75,0.25) N9(2.75,0.75) N10(2.75,1.25) N11(2.75,1.75) N12(2.75,2.25) N13(2.75,2.75) N14(2.75,3.25) P1(3.25,-3.25) P2(3.25,-2.75) P3(3.25,-2.25) P4(3.25,-1.75) P5(3.25,-1.25) P6(3.25,-0.75) P7(3.25,-0.25) P8(3.25,0.25) P9(3.25,0.75) P10(3.25,1.25) P11(3.25,1.75) P12(3.25,2.25) P13(3.25,2.75) P14(3.25,3.25)
  silkscreen extent -6.78,-6.02 6.63,5.87, body extent -6.55,-5.8 6.55,5.8, height 1
ICC_QFN12L-EPAD_3X3_P050 [mm] "MCD-01809"
  rect 0.3x0.75 smd mask+0.05: 1(-0.5,-1.425) 2(0,-1.425) 3(0.5,-1.425) 7(0.5,1.425) 8(0,1.425) 9(-0.5,1.425)
  rect 0.75x0.3 smd mask+0.05: 4(1.425,-0.5) 5(1.425,0) 6(1.425,0.5) 10(-1.425,0.5) 11(-1.425,0) 12(-1.425,-0.5)
  rect 1.7x1.7 smd mask+0.05: 13(0,0)
  body extent -1.55,-1.55 1.55,1.55, height 0.8
ICC_QFN32-EPAD_5X5_P050 [mm]
  oval 0.3x0.75 smd mask+0.05: 1(-1.75,-2.425) 2(-1.25,-2.425) 3(-0.75,-2.425) 4(-0.25,-2.425) 5(0.25,-2.425) 6(0.75,-2.425) 7(1.25,-2.425) 8(1.75,-2.425) 17(1.75,2.425) 18(1.25,2.425) 19(0.75,2.425) 20(0.25,2.425) 21(-0.25,2.425) 22(-0.75,2.425) 23(-1.25,2.425) 24(-1.75,2.425)
  oval 0.75x0.3 smd mask+0.05: 9(2.425,-1.75) 10(2.425,-1.25) 11(2.425,-0.75) 12(2.425,-0.25) 13(2.425,0.25) 14(2.425,0.75) 15(2.425,1.25) 16(2.425,1.75) 25(-2.425,1.75) 26(-2.425,1.25) 27(-2.425,0.75) 28(-2.425,0.25) 29(-2.425,-0.25) 30(-2.425,-0.75) 31(-2.425,-1.25) 32(-2.425,-1.75)
  rect 3.7x3.7 smd mask+0.05: 33(0,0)
  silkscreen extent -2.63,-2.63 2.63,2.63, body extent -2.55,-2.55 2.55,2.55, height 1
ICC_SOT23-5L_H1P45 [mm]
  rect 0.6x1.3 smd mask+0.05: 1(-0.95,-1.1) 2(0,-1.1) 3(0.95,-1.1) 4(0.95,1.1) 5(-0.95,1.1)
  silkscreen extent -1.75,-1.68 1.6,0.97, body extent -1.52,-1.25 1.52,1.25, height 1.45
ICC_TFBGA216_13X13_P080_H1P10_CODE-A0L2 [mm] "MCD-02133"
  round 0.3 smd mask+0.05: A1(-5.6,5.6) A2(-4.8,5.6) A3(-4,5.6) A4(-3.2,5.6) A5(-2.4,5.6) A6(-1.6,5.6) A7(-0.8,5.6) A8(0,5.6) A9(0.8,5.6) A10(1.6,5.6) A11(2.4,5.6) A12(3.2,5.6) A13(4,5.6) A14(4.8,5.6) A15(5.6,5.6) B1(-5.6,4.8) B2(-4.8,4.8) B3(-4,4.8) B4(-3.2,4.8) B5(-2.4,4.8) B6(-1.6,4.8) B7(-0.8,4.8) B8(0,4.8) B9(0.8,4.8) B10(1.6,4.8) B11(2.4,4.8) B12(3.2,4.8) B13(4,4.8) B14(4.8,4.8) B15(5.6,4.8) C1(-5.6,4) C2(-4.8,4) C3(-4,4) C4(-3.2,4) C5(-2.4,4) C6(-1.6,4) C7(-0.8,4) C8(0,4) C9(0.8,4) C10(1.6,4) C11(2.4,4) C12(3.2,4) C13(4,4) C14(4.8,4) C15(5.6,4) D1(-5.6,3.2) D2(-4.8,3.2) D3(-4,3.2) D4(-3.2,3.2) D5(-2.4,3.2) D6(-1.6,3.2) D7(-0.8,3.2) D8(0,3.2) D9(0.8,3.2) D10(1.6,3.2) D11(2.4,3.2) D12(3.2,3.2) D13(4,3.2) D14(4.8,3.2) D15(5.6,3.2) E1(-5.6,2.4) E2(-4.8,2.4) E3(-4,2.4) E4(-3.2,2.4) E5(-2.4,2.4) E6(-1.6,2.4) E7(-0.8,2.4) E8(0,2.4) E9(0.8,2.4) E10(1.6,2.4) E11(2.4,2.4) E12(3.2,2.4) E13(4,2.4) E14(4.8,2.4) E15(5.6,2.4) F1(-5.6,1.6) F2(-4.8,1.6) F3(-4,1.6) F4(-3.2,1.6) F5(-2.4,1.6) F6(-1.6,1.6) F7(-0.8,1.6) F8(0,1.6) F9(0.8,1.6) F10(1.6,1.6) F11(2.4,1.6) F12(3.2,1.6) F13(4,1.6) F14(4.8,1.6) F15(5.6,1.6) G1(-5.6,0.8) G2(-4.8,0.8) G3(-4,0.8) G4(-3.2,0.8) G5(-2.4,0.8) G6(-1.6,0.8) G10(1.6,0.8) G11(2.4,0.8) G12(3.2,0.8) G13(4,0.8) G14(4.8,0.8) G15(5.6,0.8) H1(-5.6,0) H2(-4.8,0) H3(-4,0) H4(-3.2,0) H5(-2.4,0) H6(-1.6,0) H10(1.6,0) H11(2.4,0) H12(3.2,0) H13(4,0) H14(4.8,0) H15(5.6,0) J1(-5.6,-0.8) J2(-4.8,-0.8) J3(-4,-0.8) J4(-3.2,-0.8) J5(-2.4,-0.8) J6(-1.6,-0.8) J10(1.6,-0.8) J11(2.4,-0.8) J12(3.2,-0.8) J13(4,-0.8) J14(4.8,-0.8) J15(5.6,-0.8) K1(-5.6,-1.6) K2(-4.8,-1.6) K3(-4,-1.6) K4(-3.2,-1.6) K5(-2.4,-1.6) K6(-1.6,-1.6) K7(-0.8,-1.6) K8(0,-1.6) K9(0.8,-1.6) K10(1.6,-1.6) K11(2.4,-1.6) K12(3.2,-1.6) K13(4,-1.6) K14(4.8,-1.6) K15(5.6,-1.6) L1(-5.6,-2.4) L2(-4.8,-2.4) L3(-4,-2.4) L4(-3.2,-2.4) L5(-2.4,-2.4) L6(-1.6,-2.4) L7(-0.8,-2.4) L8(0,-2.4) L9(0.8,-2.4) L10(1.6,-2.4) L11(2.4,-2.4) L12(3.2,-2.4) L13(4,-2.4) L14(4.8,-2.4) L15(5.6,-2.4) M1(-5.6,-3.2) M2(-4.8,-3.2) M3(-4,-3.2) M4(-3.2,-3.2) M5(-2.4,-3.2) M6(-1.6,-3.2) M7(-0.8,-3.2) M8(0,-3.2) M9(0.8,-3.2) M10(1.6,-3.2) M11(2.4,-3.2) M12(3.2,-3.2) M13(4,-3.2) M14(4.8,-3.2) M15(5.6,-3.2) N1(-5.6,-4) N2(-4.8,-4) N3(-4,-4) N4(-3.2,-4) N5(-2.4,-4) N6(-1.6,-4) N7(-0.8,-4) N8(0,-4) N9(0.8,-4) N10(1.6,-4) N11(2.4,-4) N12(3.2,-4) N13(4,-4) N14(4.8,-4) N15(5.6,-4) P1(-5.6,-4.8) P2(-4.8,-4.8) P3(-4,-4.8) P4(-3.2,-4.8) P5(-2.4,-4.8) P6(-1.6,-4.8) P7(-0.8,-4.8) P8(0,-4.8) P9(0.8,-4.8) P10(1.6,-4.8) P11(2.4,-4.8) P12(3.2,-4.8) P13(4,-4.8) P14(4.8,-4.8) P15(5.6,-4.8) R1(-5.6,-5.6) R2(-4.8,-5.6) R3(-4,-5.6) R4(-3.2,-5.6) R5(-2.4,-5.6) R6(-1.6,-5.6) R7(-0.8,-5.6) R8(0,-5.6) R9(0.8,-5.6) R10(1.6,-5.6) R11(2.4,-5.6) R12(3.2,-5.6) R13(4,-5.6) R14(4.8,-5.6) R15(5.6,-5.6)
  silkscreen extent -6.73,-6.58 6.58,6.73, body extent -6.55,-6.55 6.55,6.55, height 1.11
ICC_UDFN6-EPAD_2X2_P065 [mm] "MCD-02159"
  rect 0.27x0.7 smd mask+0.05: 1(-0.65,-0.89) 2(0,-0.89) 3(0.65,-0.89) 4(0.65,0.89) 5(0,0.89) 6(-0.65,0.89)
  rect 1.45x0.65 smd mask+0.05: 7(0,0)
  silkscreen extent -1.15,-1.33 1.02,1.02, body extent -1.03,-1.03 1.02,1.02, height 0.56
ICC_UFBGA201_176+25_10X10_P065 [mm] "IPC"
  round 0.25 smd mask+0.05: A1(-4.55,4.55) A2(-3.9,4.55) A3(-3.25,4.55) A4(-2.6,4.55) A5(-1.95,4.55) A6(-1.3,4.55) A7(-0.65,4.55) A8(0,4.55) A9(0.65,4.55) A10(1.3,4.55) A11(1.95,4.55) A12(2.6,4.55) A13(3.25,4.55) A14(3.9,4.55) A15(4.55,4.55) B1(-4.55,3.9) B2(-3.9,3.9) B3(-3.25,3.9) B4(-2.6,3.9) B5(-1.95,3.9) B6(-1.3,3.9) B7(-0.65,3.9) B8(0,3.9) B9(0.65,3.9) B10(1.3,3.9) B11(1.95,3.9) B12(2.6,3.9) B13(3.25,3.9) B14(3.9,3.9) B15(4.55,3.9) C1(-4.55,3.25) C2(-3.9,3.25) C3(-3.25,3.25) C4(-2.6,3.25) C5(-1.95,3.25) C6(-1.3,3.25) C7(-0.65,3.25) C8(0,3.25) C9(0.65,3.25) C10(1.3,3.25) C11(1.95,3.25) C12(2.6,3.25) C13(3.25,3.25) C14(3.9,3.25) C15(4.55,3.25) D1(-4.55,2.6) D2(-3.9,2.6) D3(-3.25,2.6) D4(-2.6,2.6) D5(-1.95,2.6) D6(-1.3,2.6) D7(-0.65,2.6) D8(0,2.6) D9(0.65,2.6) D10(1.3,2.6) D11(1.95,2.6) D12(2.6,2.6) D13(3.25,2.6) D14(3.9,2.6) D15(4.55,2.6) E1(-4.55,1.95) E2(-3.9,1.95) E3(-3.25,1.95) E4(-2.6,1.95) E12(2.6,1.95) E13(3.25,1.95) E14(3.9,1.95) E15(4.55,1.95) F1(-4.55,1.3) F2(-3.9,1.3) F3(-3.25,1.3) F4(-2.6,1.3) F6(-1.3,1.3) F7(-0.65,1.3) F8(0,1.3) F9(0.65,1.3) F10(1.3,1.3) F12(2.6,1.3) F13(3.25,1.3) F14(3.9,1.3) F15(4.55,1.3) G1(-4.55,0.65) G2(-3.9,0.65) G3(-3.25,0.65) G4(-2.6,0.65) G6(-1.3,0.65) G7(-0.65,0.65) G8(0,0.65) G9(0.65,0.65) G10(1.3,0.65) G12(2.6,0.65) G13(3.25,0.65) G14(3.9,0.65) G15(4.55,0.65) H1(-4.55,0) H2(-3.9,0) H3(-3.25,0) H4(-2.6,0) H6(-1.3,0) H7(-0.65,0) H8(0,0) H9(0.65,0) H10(1.3,0) H12(2.6,0) H13(3.25,0) H14(3.9,0) H15(4.55,0) J1(-4.55,-0.65) J2(-3.9,-0.65) J3(-3.25,-0.65) J4(-2.6,-0.65) J6(-1.3,-0.65) J7(-0.65,-0.65) J8(0,-0.65) J9(0.65,-0.65) J10(1.3,-0.65) J12(2.6,-0.65) J13(3.25,-0.65) J14(3.9,-0.65) J15(4.55,-0.65) K1(-4.55,-1.3) K2(-3.9,-1.3) K3(-3.25,-1.3) K4(-2.6,-1.3) K6(-1.3,-1.3) K7(-0.65,-1.3) K8(0,-1.3) K9(0.65,-1.3) K10(1.3,-1.3) K12(2.6,-1.3) K13(3.25,-1.3) K14(3.9,-1.3) K15(4.55,-1.3) L1(-4.55,-1.95) L2(-3.9,-1.95) L3(-3.25,-1.95) L4(-2.6,-1.95) L12(2.6,-1.95) L13(3.25,-1.95) L14(3.9,-1.95) L15(4.55,-1.95) M1(-4.55,-2.6) M2(-3.9,-2.6) M3(-3.25,-2.6) M4(-2.6,-2.6) M5(-1.95,-2.6) M6(-1.3,-2.6) M7(-0.65,-2.6) M8(0,-2.6) M9(0.65,-2.6) M10(1.3,-2.6) M11(1.95,-2.6) M12(2.6,-2.6) M13(3.25,-2.6) M14(3.9,-2.6) M15(4.55,-2.6) N1(-4.55,-3.25) N2(-3.9,-3.25) N3(-3.25,-3.25) N4(-2.6,-3.25) N5(-1.95,-3.25) N6(-1.3,-3.25) N7(-0.65,-3.25) N8(0,-3.25) N9(0.65,-3.25) N10(1.3,-3.25) N11(1.95,-3.25) N12(2.6,-3.25) N13(3.25,-3.25) N14(3.9,-3.25) N15(4.55,-3.25) P1(-4.55,-3.9) P2(-3.9,-3.9) P3(-3.25,-3.9) P4(-2.6,-3.9) P5(-1.95,-3.9) P6(-1.3,-3.9) P7(-0.65,-3.9) P8(0,-3.9) P9(0.65,-3.9) P10(1.3,-3.9) P11(1.95,-3.9) P12(2.6,-3.9) P13(3.25,-3.9) P14(3.9,-3.9) P15(4.55,-3.9) R1(-4.55,-4.55) R2(-3.9,-4.55) R3(-3.25,-4.55) R4(-2.6,-4.55) R5(-1.95,-4.55) R6(-1.3,-4.55) R7(-0.65,-4.55) R8(0,-4.55) R9(0.65,-4.55) R10(1.3,-4.55) R11(1.95,-4.55) R12(2.6,-4.55) R13(3.25,-4.55) R14(3.9,-4.55) R15(4.55,-4.55)
  silkscreen extent -5.22,-5.07 5.07,5.23, body extent -5.07,-5.07 5.07,5.07, height 0.61
ICC_VQFN16-EPAD_3X3_P050 [mm] "MCD-02580"
  rect 0.3x0.8 smd mask+0.05: 1(-0.75,-1.5) 2(-0.25,-1.5) 3(0.25,-1.5) 4(0.75,-1.5) 9(0.75,1.5) 10(0.25,1.5) 11(-0.25,1.5) 12(-0.75,1.5)
  rect 0.8x0.3 smd mask+0.05: 5(1.5,-0.75) 6(1.5,-0.25) 7(1.5,0.25) 8(1.5,0.75) 13(-1.5,0.75) 14(-1.5,0.25) 15(-1.5,-0.25) 16(-1.5,-0.75)
  rect 1.8x1.8 smd mask+0.05: 17(0,0)
  silkscreen extent -1.58,-1.58 1.58,1.58, body extent -1.58,-1.58 1.58,1.58, height 1
ICC_VSSOP8_DCU_R-PDSO-G8_2X2P30_P050 [mm]
  rect 0.3x0.8 smd mask+0.05: 1(-0.75,-1.55) 2(-0.25,-1.55) 3(0.25,-1.55) 4(0.75,-1.55) 5(0.75,1.55) 6(0.25,1.55) 7(-0.25,1.55) 8(-0.75,1.55)
  silkscreen extent -1.05,-1.2 1.05,1.2, body extent -1.05,-1.62 1.05,1.62, height 0.9
IND_0402_MURATA_BLM15H_H0P5 [mm] "MCD-01610"
  rect 0.65x0.9 smd mask+0.05: 1(-0.475,0) 2(0.475,0)
  body extent -0.53,-0.28 0.53,0.28, height 0.55
IND_COILCRAFT_XGL4020 [mm] "MCD-02582"
  rect 3.4x1 smd mask+0.05: 1(0,1.185) 2(0,-1.185)
  silkscreen extent -2.15,-2.15 2.15,2.4, body extent -2.15,-2.15 2.15,2.15, height 2.11
L0603 [mm]
  rect 0.8x0.95 smd mask+0.05: 1(-0.8,0) 2(0.8,0)
  silkscreen extent -1.33,-0.6 1.33,0.6, body extent -0.87,-0.47 0.87,0.47, height 0.95
L0805_H0P9 [mm]
  rect 1.1x1.6 smd mask+0.05: 1(-0.75,0) 2(0.75,0)
  silkscreen extent -0.08,-0.7 0.08,0.7, body extent -1.07,-0.7 1.07,0.7, height 1.2
LED_0603_OSRAM_LG-Q396-PS-35_GREEN_1A2K_H0P4 [mm]
  rect 0.8x0.8 smd mask+0.05: 1(-0.75,0) 2(0.75,0)
  silkscreen extent -0.85,-0.53 1.28,0.53, body extent -0.85,-0.45 0.85,0.45, height 0.6
LED_0603_OSRAM_LS-Q976-NR-1_RED_1A2K_H0P8 [mm]
  rect 0.8x0.8 smd mask+0.05: 1(-0.75,0) 2(0.75,0)
  silkscreen extent -0.85,-0.53 1.28,0.53, body extent -0.85,-0.45 0.85,0.45, height 0.8
LED_BI-GR_WE-150141SV73110 [mm] "MCD-02631"
  rect 1.1x1.5 smd mask+0.05: 1(-0.75,1.5) 2(0.75,1.5) 3(-0.75,-1.5) 4(0.75,-1.5)
  silkscreen extent -1.65,-1.85 1.5,1.7, body extent -1.5,-1.85 1.5,1.85, height 2.1
MOS_POWERFLAT_3P3X3P3_P065 [mm] "MCD-01126"
  rect 0.4x0.75 smd mask+0.05: 1(-0.975,-1.525) 2(-0.325,-1.525) 3(0.325,-1.525) 4(0.975,-1.525) 6(0.325,1.525) 7(-0.325,1.525)
  rect 0.45x0.75 smd mask+0.05: 5(1,1.525) 8(-1,1.525)
  Top Layer region: -1.755,0.2 -1.755,-0.2 -1.225,-0.2 -1.225,-0.5 1.225,-0.5 1.225,-0.2 1.755,-0.2 1.755,0.2 1.225,0.2 1.225,1.9 -1.225,1.9 -1.225,0.2
  silkscreen extent -1.63,-1.55 1.63,1.55, body extent -1.75,-1.75 1.75,1.75, height 0.91
MOS_SOT23-5L [mm]
  rect 0.6x1.3 smd mask+0.05: 1(-0.95,-1.1) 2(0,-1.1) 3(0.95,-1.1) 4(0.95,1.1) 5(-0.95,1.1)
  silkscreen extent -1.6,-0.95 1.6,0.97, body extent -1.52,-1.25 1.52,1.25, height 1.45
MOS_SOT23-6L [mm]
  rect 0.6x1.2 smd mask+0.05: 1(-0.95,-1.15) 2(0,-1.15) 3(0.95,-1.15) 4(0.95,1.15) 5(0,1.15) 6(-0.95,1.15)
  silkscreen extent -1.53,-0.87 1.53,0.87, body extent -1.52,-1.5 1.52,1.5, height 1.3
NPN_SOT23 [mm]
  rect 1x1.4 smd mask+0.05: 1(-0.95,-1.1) 2(0.95,-1.1) 3(0,1.1)
  silkscreen extent -1.63,-0.82 1.63,0.82, body extent -1.56,-1.25 1.56,1.25, height 1.1
OSC_NDK_NZ2520SB_4P [mm]
  rect 1x1 smd mask+0.05: 1(-0.825,-0.625) 2(0.825,-0.625) 3(0.825,0.625) 4(-0.825,0.625)
  silkscreen extent -1.43,-1.22 1.2,1.05, body extent -1.3,-1.05 1.3,1.05, height 0.91
PTH_350_500 [mm]
  round 5 hole 3.5 mask+0.1: PTH1(0,0)
  silkscreen extent -2.8,-2.8 2.8,2.8
PTH_350_700_H-12 [mm]
  round 7 hole 3.5 mask+0.05: 1(0,0)
  silkscreen extent -3.7,-3.7 3.7,3.7, body extent -2,-2 2,2, height 12
PTH_450_900 [mm] "MCD-01612"
  round 9 hole 4.5 mask+0.05: 1(0,0)
  silkscreen extent -4.75,-4.75 4.75,4.75
R0402 [mm]
  rect 0.51x0.7 smd mask+0.05: 1(-0.45,0) 2(0.45,0)
  body extent -0.52,-0.3 0.52,0.3, height 0.4
R0603 [mm]
  rect 0.64x1 smd mask+0.05: 1(-0.7,0) 2(0.7,0)
  silkscreen extent -1.05,-0.58 1.05,0.58, body extent -0.9,-0.5 0.9,0.5, height 0.56
REG_SOT23-5L [mm]
  rect 0.6x1.3 smd mask+0.05: 1(-0.95,-1.1) 2(0,-1.1) 3(0.95,-1.1) 4(0.95,1.1) 5(-0.95,1.1)
  silkscreen extent -1.6,-0.95 1.6,0.97, body extent -1.52,-1.25 1.52,1.25, height 1.1
SOLDER-BRIDGE_R0402-0R [mil] "MCD-01619"
  round 10 smd paste-393.7: 1(-17.72,0) 2(20.67,0)
  Top Layer region: 1.48,13.78 8.37,0 1.48,-13.78 30.51,-13.78 30.51,13.78
  Top Layer region: -30.51,-13.78 -30.51,13.78 -8.86,13.78 -2.95,0 -8.86,-13.78
  silkscreen extent -33,-17 33,17, body extent -20,-12 20,12, height 14
STICKER_BOARD_25X9 [mm] "Sticker to mention board CPN code"
  silkscreen extent -12.5,-4.5 12.5,4.5
STICKER_ES_6X6 [mm] "Sticker to mention board QR code 8X8"
  silkscreen extent -3,-3 3,3
STICKER_PRODUCT_25X5 [mm] "Sticker to mention board CPN code"
  silkscreen extent -12.5,-2.5 12.5,2.5
SWI_C&K_KSC321JLFS_BLACK [mm] "MCD-01799"
  rect 3.1x1 smd mask+0.05: 1(-2.8,2) 2(2.8,2) 3(-2.8,-2) 4(2.8,-2)
  silkscreen extent -3.25,-3.25 3.25,3.25, body extent -3.4,-3.25 3.4,3.25, height 3.5
SWI_C&K_KSC721JLFS_BLUE [mm] "MCD-01800"
  rect 3.1x1 smd mask+0.05: 1(-2.8,2) 2(2.8,2) 3(-2.8,-2) 4(2.8,-2)
  silkscreen extent -3.25,-3.25 3.25,3.25, body extent -3.4,-3.25 3.4,3.25, height 4.3
SWI_EAO_09-03290-01_EXTENDED_STRAIGHT_BLACK [mm]
  rect 1.7x1.7 hole 0.9 mask+0.05: 1(0,0)
  round 1.7 hole 0.9 mask+0.05: 2(0,-2.54) 3(0,2.54)
  silkscreen extent -1.25,-5 1.25,5, body extent -1.25,-5 1.25,5, height 7.9
TP_SMD_1MM [mm]
  round 1 smd paste-10 mask+0.05: 1(0,0)
  silkscreen extent -0.7,-0.7 0.7,0.7

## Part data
B1: library part MCD-01800, "Switch HW BLUE High4.3mm 2.25 Newtons, BEND type", Manufacturer=C&K, Manufacturer_Part_Number=KSC721JLFS
B2: library part MCD-01799, "Switch HW BLACK High3.5mm 2Newtons, BEND type", Manufacturer=C&K, Manufacturer_Part_Number=KSC321JLFS
C1 C2 C5 C8 C12 C13 C20 C22 C23 C24 C27 C28 C29 C30 C34 C36 C37 C38 C39 C40 C42 C43 C45 C46 C47 C49 C50 C51 C53 C55 C56 C58 C60 C61 C62 C63 C64 C65 C66 C69 C70 C71 C72 C73 C74 C75 C76 C77 C80 C83 C85 C86 C87 C88 C89 C91 C92 C99 C100 C101 C103 C104 C107 C108 C109 C120 C130 C135 C139 C143 C144 C145 C146 C148: library part MCD-00006, "Capacitor, MLCC, 100nF, 16V, X7R, +/-10%, 0402, T=0.5mm", Manufacturer=YAGEO, Manufacturer_Part_Number=CC0402KRX7R7BB104, Package=0402
C3 C4: library part MCD-00304, "Capacitor, MLCC, 150pF, 50V, COG, +/-5%, 0603, T=0.8mm", Manufacturer=YAGEO, Manufacturer_Part_Number=CC0603JRNPO9BN151, Package=0603
C6 C9 C10 C11 C19 C41 C48: library part MCD-01722, "Capacitor, MLCC, 1uF, 10V, X5R, +/-10%, 0402, T=0.5mm", Manufacturer=YAGEO, Manufacturer_Part_Number=CC0402KRX5R6BB105, Package=0402
C7: library part MCD-00243, "Capacitor, MLCC, 10uF, 6V3, X5R, +/-10%, 0603, T=0.8mm", Manufacturer=YAGEO, Manufacturer_Part_Number=CC0603KRX5R5BB106, Package=0603
C14 C15: library part MCD-00202, "Capacitor, MLCC, 22nF, 16V, X7R, +/-10%, 0402, T=0.5mm", Manufacturer=YAGEO, Manufacturer_Part_Number=CC0402KRX7R7BB223, Package=0402
C16 C17: library part MCD-00010, "Capacitor, MLCC, 1uF, 16V, X5R, +/-10%, 0603, T=0.8mm", Manufacturer=YAGEO, Manufacturer_Part_Number=CC0603KRX5R7BB105, Package=0603
C18 C113: library part MCD-00211, "Capacitor, MLCC, 100nF, 16V, X7R, +/-10%, 0603, T=0.8mm", Alternate_Manufacturer=N/A, Manufacturer=YAGEO, Manufacturer_Part_Number=CC0603KRX7R7BB104, Package=0603
C21: library part MCD-01721, "Capacitor, MLCC, 4.7uF, 10V, X5R, +/-10%, 0603, T=0.8mm", Alternate_Manufacturer=N/A, Manufacturer=YAGEO, Manufacturer_Part_Number=CC0603KRX5R6BB475, Package=0603
C25 C125: library part MCD-00211, "Capacitor, MLCC, 100nF, 16V, X7R, +/-10%, 0603, T=0.8mm", Manufacturer=YAGEO, Manufacturer_Part_Number=CC0603KRX7R7BB104, Package=0603
C26 C31 C35 C106: library part MCD-00009, "Capacitor, MLCC, 4.7uF, 16V, X5R, +/-10%, 0603, T=0.8mm", Manufacturer=YAGEO, Manufacturer_Part_Number=CC0603KRX5R7BB475, Package=0603
C32 C33: library part MCD-01932, "Capacitor, MLCC, 8.2pF, 50V, NPO, +/-0.25pF, 0402, T=0.5mm", Manufacturer=YAGEO, Manufacturer_Part_Number=CC0402CRNPO9BN8R2, Package=0402
C44 C140: library part MCD-02606, "Capacitor, MLCC, 2.2uF, 6.3V, X5R, +/-10%, 0402, T=0.5mm", Manufacturer=YAGEO, Manufacturer_Part_Number=CC0402KRX5R5BB225, Package=0402
C52 C84 C97 C115 C116 C117 C118: library part MCD-02605, "Capacitor, MLCC, 10uF, 10V, X5R, +/-10%, 0603, T=0.8mm", Manufacturer=YAGEO, Manufacturer_Part_Number=CC0603KRX5R6BB106, Package=0603
C54: library part MCD-01716, "Capacitor, MLCC, 10uF, 6V3, X5R, +/-20%, 0402, T=0.5mm", Manufacturer=YAGEO, Manufacturer_Part_Number=CC0402MRX5R5BB106, Package=0402
C57 C67 C78 C95 C110 C137: library part MCD-00012, "Capacitor, MLCC, 2.2uF, 10V, X5R, +/- 10%, 0603, T=0.8mm", Manufacturer=YAGEO, Manufacturer_Part_Number=CC0603KRX5R6BB225, Package=0603
C59: library part MCD-00637, "Capacitor, MLCC, 10pF, 50V, NPO, +/-5%, 0603, T=0.8mm", Manufacturer=YAGEO, Manufacturer_Part_Number=CC0603JRNPO9BN100, Package=0603
C68: library part MCD-02608, "Capacitor, MLCC, 4.7uF, 6.3V, X5R, +/-10%, 0402, T=0.5mm", Manufacturer=YAGEO, Manufacturer_Part_Number=CC0402KRX5R5BB475, Package=0402
C79 C90: library part MCD-01579, "Capacitor, MLCC, 330pF, 50V, NPO, +/-5%, 0402, T=0.5mm", Manufacturer=YAGEO, Manufacturer_Part_Number=CC0402JRNPO9BN331, Package=0402
C81 C105: library part MCD-01099, "Capacitor, MLCC, 100nF, 50V, X7R, +/-10%, 0603, T=0.8mm", Manufacturer=YAGEO, Manufacturer_Part_Number=CC0603KRX7R9BB104, Package=0603
C82 C138: library part MCD-00016, "Capacitor, MLCC, 20pF, 50V, NPO, +/- 5%, 0402, T=0.5mm", Manufacturer=YAGEO, Manufacturer_Part_Number=CC0402JRNPO9BN200, Package=0402
C93 C112: library part MCD-00205, "Capacitor, MLCC, 100pF, 50V, NPO, +/-5%, 0402, T=0.5mm", Manufacturer=YAGEO, Manufacturer_Part_Number=CC0402JRNPO9BN101, Package=0402
C94 C98 C102 C111 C141 C142: library part MCD-02609, "Capacitor, MLCC, 1uF, 25V, X5R, +/-10%, 0402, T=0.5mm", Manufacturer=YAGEO, Manufacturer_Part_Number=CC0402KRX5R8BB105, Package=0402
C96: library part MCD-00011, "Capacitor, MLCC, 10nF, 16V, X7R, +/-10%, 0402, T=0.5mm", Manufacturer=YAGEO, Manufacturer_Part_Number=CC0402KRX7R7BB103, Package=0402
C114: library part MCD-00012, "Capacitor, MLCC, 2.2uF, 10V, X5R, +/- 10%, 0603, T=0.8mm", Alternate_Manufacturer=KEMET, Alternate_Manufacturer_Part_Number=C0603C225K8PACTU, Manufacturer=YAGEO, Manufacturer_Part_Number=CC0603KRX5R6BB225, Package=0603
